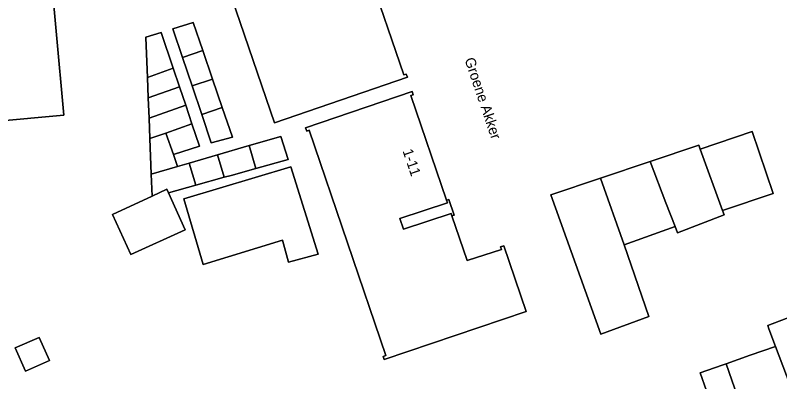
# Model space of a CAD drawing. Extents: x 159371 to 159986, y 382987 to 383597.
# Drawn here: x 159771.8 to 159845.8, y 383368 to 383403.5 of the extents above; entities that cross this region are included whole.
import ezdxf

# ---------------------------------------------------------------- set-up
doc = ezdxf.new("R2010")
doc.units = 0
for name, color, linetype in [('IMGEO_Erf', 7, 'Continuous'), ('IMGEO_Openbare_ruimte_label', 7, 'Continuous'), ('IMGEO_Pand', 7, 'Continuous'), ('IMGEO_Pand_nummerreeks', 7, 'Continuous'), ('IMGEO_Voetpad_op_trap', 7, 'Continuous')]:
    doc.layers.add(name, color=color, linetype=linetype)

msp = doc.modelspace()

# ---------------------------------------------------------------- linework, layer by layer
at = {"layer": 'IMGEO_Erf'}
for points in [[(159802.443, 383426.11), (159803.551, 383426.483), (159805.549, 383420.55), (159804.441, 383420.177), (159804.526, 383419.932), (159803.77, 383419.669), (159803.685, 383419.915), (159802.006, 383419.331), (159805.408, 383409.347), (159805.646, 383409.426), (159806.168, 383407.892), (159805.931, 383407.814), (159809.378, 383397.699), (159809.618, 383397.783), (159809.724, 383397.481), (159796.842, 383393.077), (159787.292, 383421.008)], [(159774.241, 383418.212), (159776.47, 383393.811), (159735.813, 383390.097), (159733.584, 383414.498)], [(159790.857, 383397.306), (159791.805, 383394.552), (159792.789, 383391.694), (159790.74, 383391.117), (159789.808, 383393.877), (159788.876, 383396.638), (159787.944, 383399.398), (159787.012, 383402.158), (159788.98, 383402.759), (159789.909, 383400.061)], [(159785.875, 383401.81), (159787.05, 383398.343), (159787.658, 383396.548), (159788.261, 383394.77), (159788.868, 383392.978), (159789.607, 383390.797), (159787.071, 383389.988), (159787.477, 383388.841), (159788.605, 383389.17), (159791.346, 383389.969), (159794.399, 383390.86), (159797.482, 383391.759), (159798.177, 383389.516), (159795.047, 383388.641), (159792.665, 383387.975), (159792.662, 383387.985), (159791.981, 383387.795), (159789.231, 383387.026), (159786.6, 383386.29), (159788.208, 383382.717), (159782.932, 383380.31), (159781.163, 383384.188), (159785.015, 383385.982), (159784.932, 383388.099), (159784.797, 383391.537), (159784.719, 383393.516), (159784.642, 383395.479), (159784.564, 383397.464), (159784.414, 383401.275), (159784.411, 383401.363)], [(159810.192, 383396.102), (159810.296, 383395.789), (159810.051, 383395.708), (159813.511, 383385.584), (159813.738, 383385.66), (159814.262, 383384.127), (159814.034, 383384.051), (159815.509, 383379.736), (159818.821, 383380.801), (159818.736, 383381.063), (159819.072, 383381.162), (159821.228, 383374.818), (159807.483, 383370.157), (159807.378, 383370.465), (159807.624, 383370.549), (159800.22, 383392.344), (159799.974, 383392.26), (159799.869, 383392.567)], [(159843.11, 383392.215), (159845.116, 383386.23), (159840.221, 383384.589), (159840.38, 383384.152), (159835.874, 383382.43), (159835.635, 383383.05), (159830.719, 383381.268), (159833.108, 383374.317), (159828.455, 383372.618), (159823.591, 383386.102), (159828.421, 383387.721), (159833.221, 383389.329), (159837.923, 383390.905), (159838.062, 383390.523)], [(159798.433, 383388.808), (159801.069, 383380.372), (159798.213, 383379.597), (159797.642, 383381.699), (159789.954, 383379.355), (159788.085, 383385.727)], [(159774.088, 383372.303), (159775.064, 383370.055), (159772.74, 383369.046), (159771.764, 383371.293)]]:
    msp.add_lwpolyline(points, close=True, dxfattribs=at)
msp.add_lwpolyline([(159838.672, 383367.139), (159838.064, 383368.889), (159840.192, 383369.628), (159840.573, 383369.76), (159842.919, 383370.575), (159845.368, 383371.426), (159844.726, 383373.135), (159844.604, 383373.459), (159849.507, 383375.324)], dxfattribs=at)
at = {"layer": 'IMGEO_Pand'}
for points in [[(159802.006, 383419.331), (159803.685, 383419.915), (159803.77, 383419.669), (159804.526, 383419.932), (159804.441, 383420.177), (159802.443, 383426.11), (159787.292, 383421.008), (159796.842, 383393.077), (159809.724, 383397.481), (159809.618, 383397.783), (159809.378, 383397.699), (159805.931, 383407.814), (159805.847, 383408.059), (159801.267, 383406.545), (159800.911, 383407.589), (159805.492, 383409.102), (159805.408, 383409.347)], [(159774.241, 383418.212), (159733.584, 383414.498), (159735.813, 383390.097), (159776.47, 383393.811)], [(159788.98, 383402.759), (159787.012, 383402.158), (159787.944, 383399.398), (159789.909, 383400.061)], [(159785.875, 383401.81), (159784.411, 383401.363), (159784.414, 383401.275), (159784.564, 383397.464), (159787.05, 383398.343)], [(159789.909, 383400.061), (159787.944, 383399.398), (159788.876, 383396.638), (159790.857, 383397.306)], [(159787.05, 383398.343), (159784.564, 383397.464), (159784.642, 383395.479), (159787.658, 383396.548)], [(159790.857, 383397.306), (159788.876, 383396.638), (159789.808, 383393.877), (159791.805, 383394.552)], [(159787.658, 383396.548), (159784.642, 383395.479), (159784.719, 383393.516), (159788.261, 383394.77)], [(159810.051, 383395.708), (159810.296, 383395.789), (159810.192, 383396.102), (159799.869, 383392.567), (159799.974, 383392.26), (159800.22, 383392.344), (159807.624, 383370.549), (159807.378, 383370.465), (159807.483, 383370.157), (159821.228, 383374.818), (159819.072, 383381.162), (159818.736, 383381.063), (159818.821, 383380.801), (159815.509, 383379.736), (159814.034, 383384.051), (159813.951, 383384.296), (159809.356, 383382.771), (159809, 383383.814), (159813.594, 383385.339), (159813.511, 383385.584)], [(159788.261, 383394.77), (159784.719, 383393.516), (159784.797, 383391.537), (159786.33, 383392.08), (159788.868, 383392.978)], [(159791.805, 383394.552), (159789.808, 383393.877), (159790.74, 383391.117), (159792.789, 383391.694)], [(159788.868, 383392.978), (159786.33, 383392.08), (159787.071, 383389.988), (159789.607, 383390.797)], [(159787.071, 383389.988), (159786.33, 383392.08), (159784.797, 383391.537), (159784.932, 383388.099), (159787.477, 383388.841)], [(159797.482, 383391.759), (159794.399, 383390.86), (159795.047, 383388.641), (159798.177, 383389.516)], [(159838.062, 383390.523), (159840.221, 383384.589), (159845.116, 383386.23), (159843.11, 383392.215)], [(159794.399, 383390.86), (159791.346, 383389.969), (159791.981, 383387.795), (159792.662, 383387.985), (159792.665, 383387.975), (159795.047, 383388.641)], [(159838.062, 383390.523), (159837.923, 383390.905), (159833.221, 383389.329), (159834.725, 383385.327), (159834.751, 383385.337), (159835.635, 383383.05), (159835.874, 383382.43), (159840.38, 383384.152), (159840.221, 383384.589)], [(159791.346, 383389.969), (159788.605, 383389.17), (159789.231, 383387.026), (159791.981, 383387.795)], [(159788.605, 383389.17), (159787.477, 383388.841), (159784.932, 383388.099), (159785.015, 383385.982), (159786.44, 383386.646), (159786.6, 383386.29), (159789.231, 383387.026)], [(159798.433, 383388.808), (159788.085, 383385.727), (159789.954, 383379.355), (159797.642, 383381.699), (159798.213, 383379.597), (159801.069, 383380.372)], [(159833.221, 383389.329), (159828.421, 383387.721), (159830.719, 383381.268), (159835.635, 383383.05), (159834.751, 383385.337), (159834.725, 383385.327)], [(159830.719, 383381.268), (159828.421, 383387.721), (159823.591, 383386.102), (159828.455, 383372.618), (159833.108, 383374.317)], [(159786.6, 383386.29), (159786.44, 383386.646), (159785.015, 383385.982), (159781.163, 383384.188), (159782.932, 383380.31), (159788.208, 383382.717)], [(159850.332, 383373.15), (159850.322, 383373.18), (159849.63, 383375), (159849.507, 383375.324), (159844.604, 383373.459), (159844.726, 383373.135), (159845.368, 383371.426), (159846.769, 383367.697), (159846.807, 383367.595), (159849.765, 383359.071), (159853.295, 383360.297), (159853.064, 383360.962), (159854.41, 383361.429)], [(159771.764, 383371.293), (159772.74, 383369.046), (159775.064, 383370.055), (159774.088, 383372.303)], [(159846.807, 383367.595), (159846.769, 383367.697), (159845.368, 383371.426), (159842.919, 383370.575), (159840.573, 383369.76), (159844.638, 383358.043), (159846.002, 383358.517), (159846.235, 383357.845), (159849.765, 383359.071)], [(159840.573, 383369.76), (159840.192, 383369.628), (159838.064, 383368.889), (159838.672, 383367.139), (159839.366, 383365.141), (159836.92, 383364.291), (159836.985, 383364.113), (159839.937, 383355.612), (159843.522, 383356.857), (159843.274, 383357.57), (159844.638, 383358.043)]]:
    msp.add_lwpolyline(points, close=True, dxfattribs=at)
at = {"layer": 'IMGEO_Voetpad_op_trap'}
msp.add_lwpolyline([(159813.951, 383384.296), (159814.034, 383384.051), (159814.262, 383384.127), (159813.738, 383385.66), (159813.511, 383385.584), (159813.594, 383385.339), (159809, 383383.814), (159809.356, 383382.771)], close=True, dxfattribs=at)

# ---------------------------------------------------------------- texts
at = {"layer": 'IMGEO_Openbare_ruimte_label'}
msp.add_text('Groene Akker', height=1, rotation=288.67058, dxfattribs=at).set_placement((159815.242, 383399.192))
at = {"layer": 'IMGEO_Pand_nummerreeks'}
msp.add_text('1-11', height=1, rotation=288.86729, dxfattribs=at).set_placement((159809.242, 383390.345))

doc.saveas('drawing.dxf')
